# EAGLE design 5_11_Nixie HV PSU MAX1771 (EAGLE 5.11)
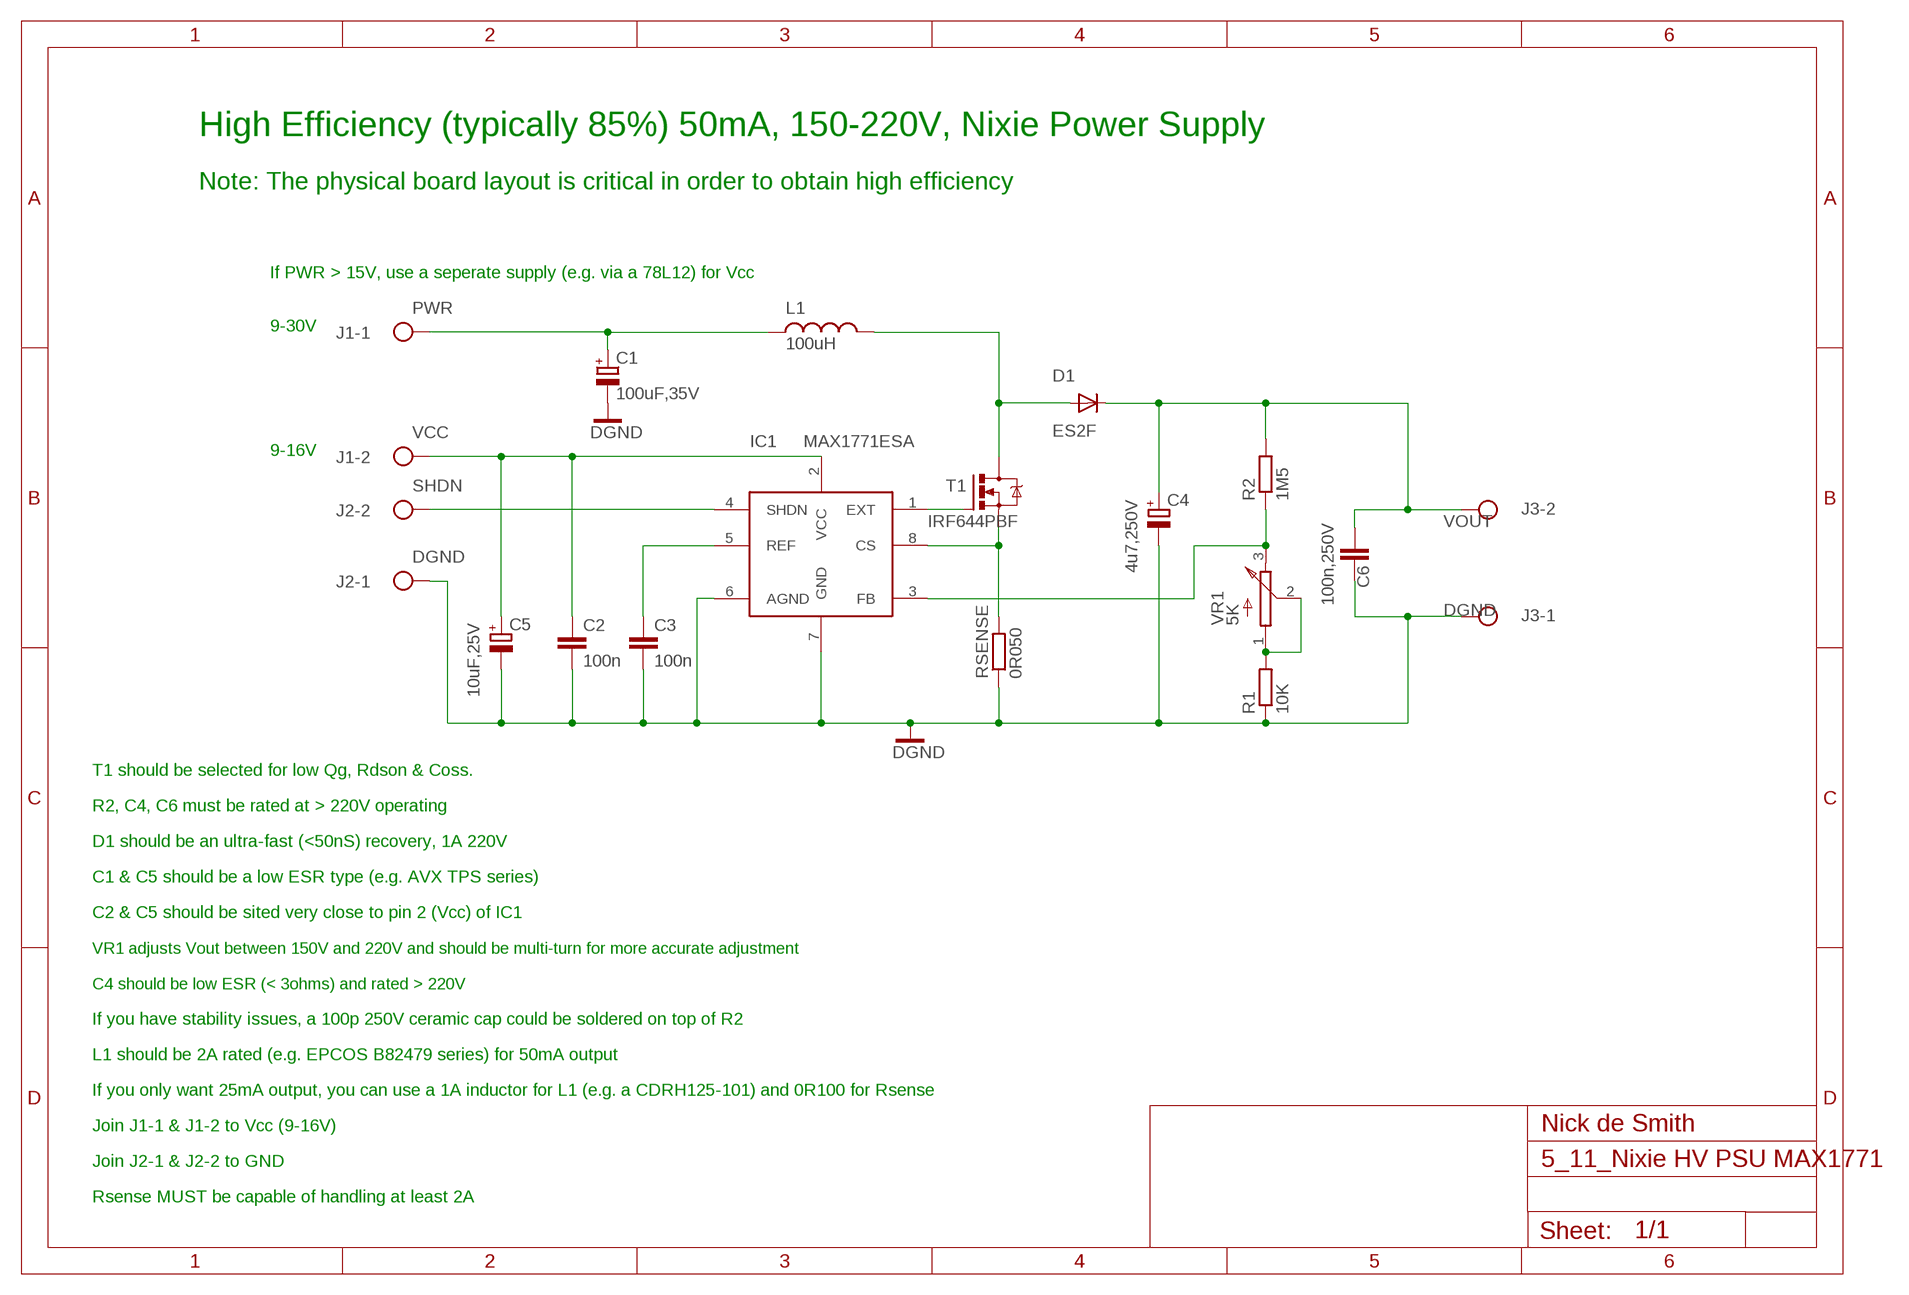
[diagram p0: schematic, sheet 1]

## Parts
C1  100uF,35V  C-POL-EU7343  [C-EIA-7343]
C2  100n  C-EUC0805  [C0805]
C3  100n  C-EUC0805  [C0805]
C4  4u7,250V  C-POL-EU-NICHICON-UJ-12  [NICHICON-UJ-12]
C5  10uF,25V  C-POL-EU7343  [C-EIA-7343]
C6  100n,250V  C-EU-2420  [C2420]
D1  ES2F  DIODE-SMC  [SMC]
IC1  MAX1771ESA  [SO-8]
J1  TERM-BLOCK-2-02IN  [SCREW-2-02]
J2  TERM-BLOCK-2-02IN  [SCREW-2-02]
J3  TERM-BLOCK-2-02IN  [SCREW-2-02]
L1  100uH  L-SMT-POWER-B82479  [L-B82479]
R1  10K  R-EU_R0805  [R0805]
R2  1M5  R-EU_R2512  [R2512]
RSENSE  0R050  R-EU_R2010  [R2010]
T1  IRF644PBF  IRF740  [TO220BV]
VR1  5K  TRIMPOT-3214W  [BOURNS-3214W]

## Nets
DGND [power]: C1.- C2.2 C3.2 C4.1(-) C5.- C6.P$2 IC1.6(AGND) IC1.7(GND) J2.1 J3.1 R1.1 RSENSE.1
EXT: IC1.1(EXT) T1.G
N$2: IC1.8(CS) RSENSE.2 T1.S
N$3: R1.2 VR1.1(A) VR1.2(W)
N$8: IC1.3(FB) R2.1 VR1.3(B)
N$15 [power]: D1.A L1.P$2 T1.D
N$17: C3.1 IC1.5(REF)
PWR [power]: C1.+ J1.1 L1.P$1
SHDN: IC1.4(SHDN) J2.2
VCC [power]: C2.1 C5.+ IC1.2(VCC) J1.2
VOUT [power]: C4.2(+) C6.P$1 D1.C J3.2 R2.2

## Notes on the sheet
- High Efficiency (typically 85%) 50mA, 150-220V, Nixie Power Supply
- Note: The physical board layout is critical in order to obtain high efficiency
- If PWR > 15V, use a seperate supply (e.g. via a 78L12) for Vcc
- 9-30V
- 9-16V
- T1 should be selected for low Qg, Rdson & Coss.
- R2, C4, C6 must be rated at > 220V operating
- D1 should be an ultra-fast (<50nS) recovery, 1A 220V
- C1 & C5 should be a low ESR type (e.g. AVX TPS series)
- C2 & C5 should be sited very close to pin 2 (Vcc) of IC1
- VR1 adjusts Vout between 150V and 220V and should be multi-turn for more accurate adjustment
- C4 should be low ESR (< 3ohms) and rated > 220V
- If you have stability issues, a 100p 250V ceramic cap could be soldered on top of R2
- L1 should be 2A rated (e.g. EPCOS B82479 series) for 50mA output
- If you only want 25mA output, you can use a 1A inductor for L1 (e.g. a CDRH125-101) and 0R100 for Rsense
- Join J1-1 & J1-2 to Vcc (9-16V) | Nick de Smith
- Join J2-1 & J2-2 to GND
- Rsense MUST be capable of handling at least 2A

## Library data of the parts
C1 C5 = nick:C-POL-EU7343: Capacitor, Tantalum, EU 7343 case, polarised
C2 C3 = rcl:C-EU: CAPACITOR, European symbol
C4 = nick:C-POL-EU: Capacitor, Tantalum, EU 7343 case, polarised
C6 = nick:C-EU
D1 = diode:DIODE-: DIODE
IC1 = nick:MAX1771
J1-J3 = nick:TERM-BLOCK-2
L1 = nick:L-SMT-POWER: SMT power inductors
R1 R2 RSENSE = rcl:R-EU_: RESISTOR, European symbol
T1 = transistor-power:IRF740: N-CHANNEL MOS FET
VR1 = nick:TRIMPOT

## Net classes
1 power: width 0.762 mm, clearance 0.508 mm

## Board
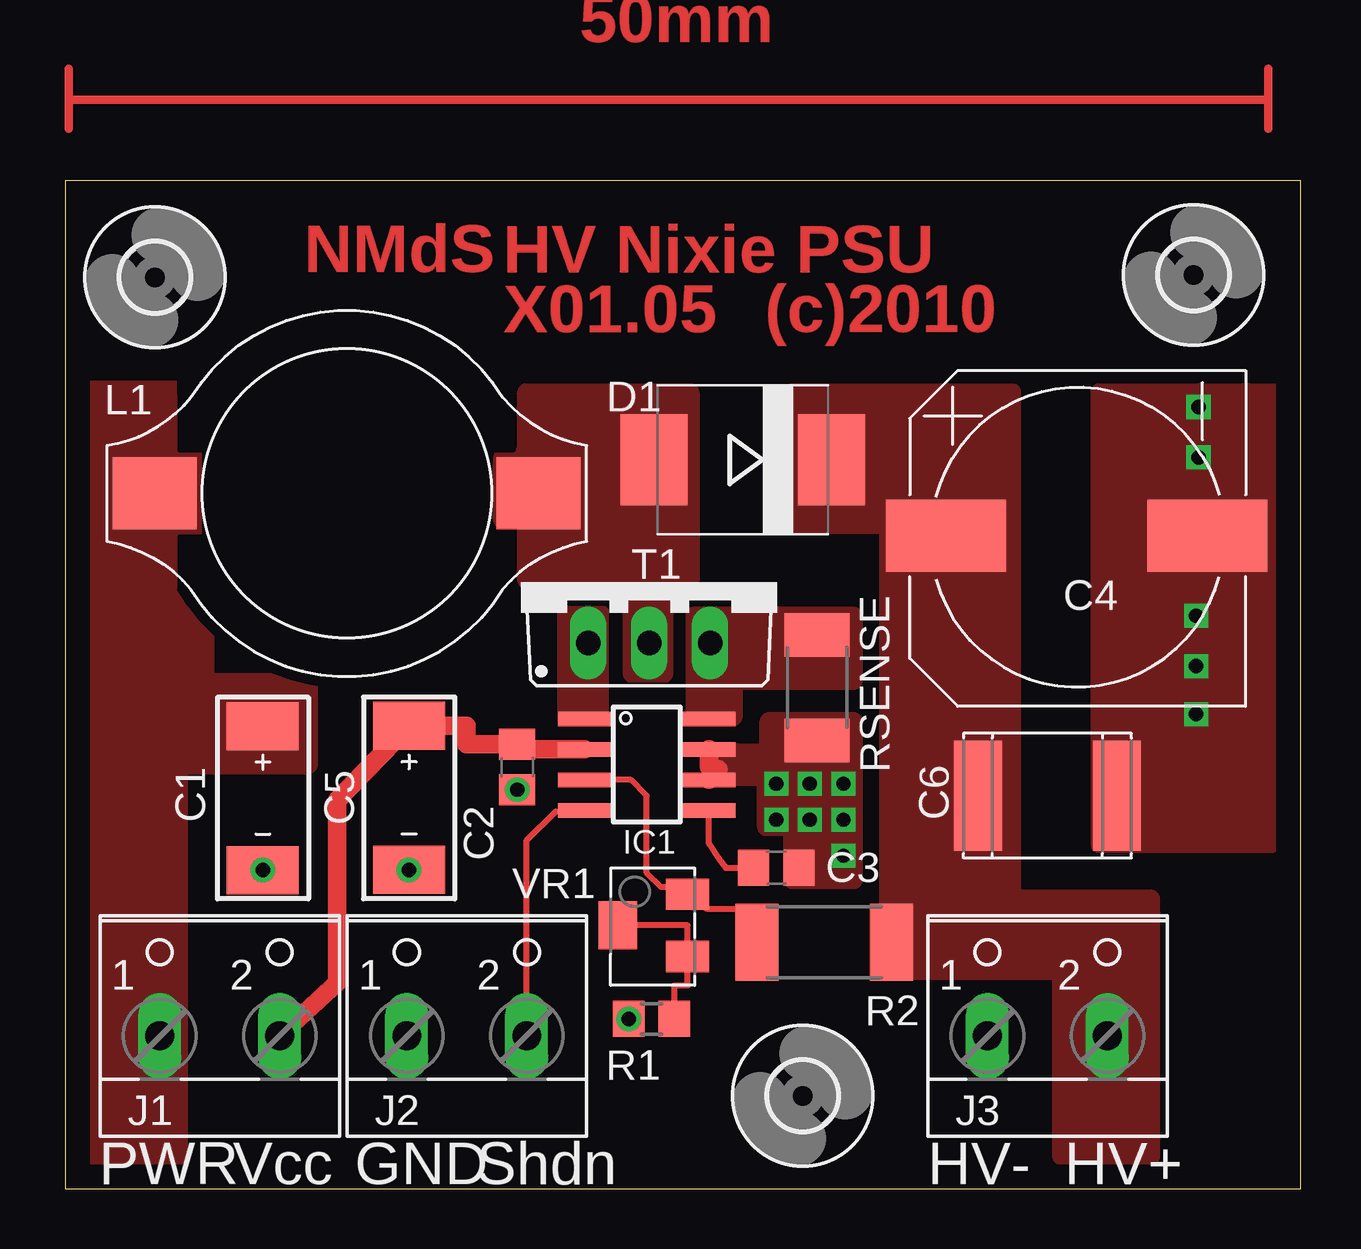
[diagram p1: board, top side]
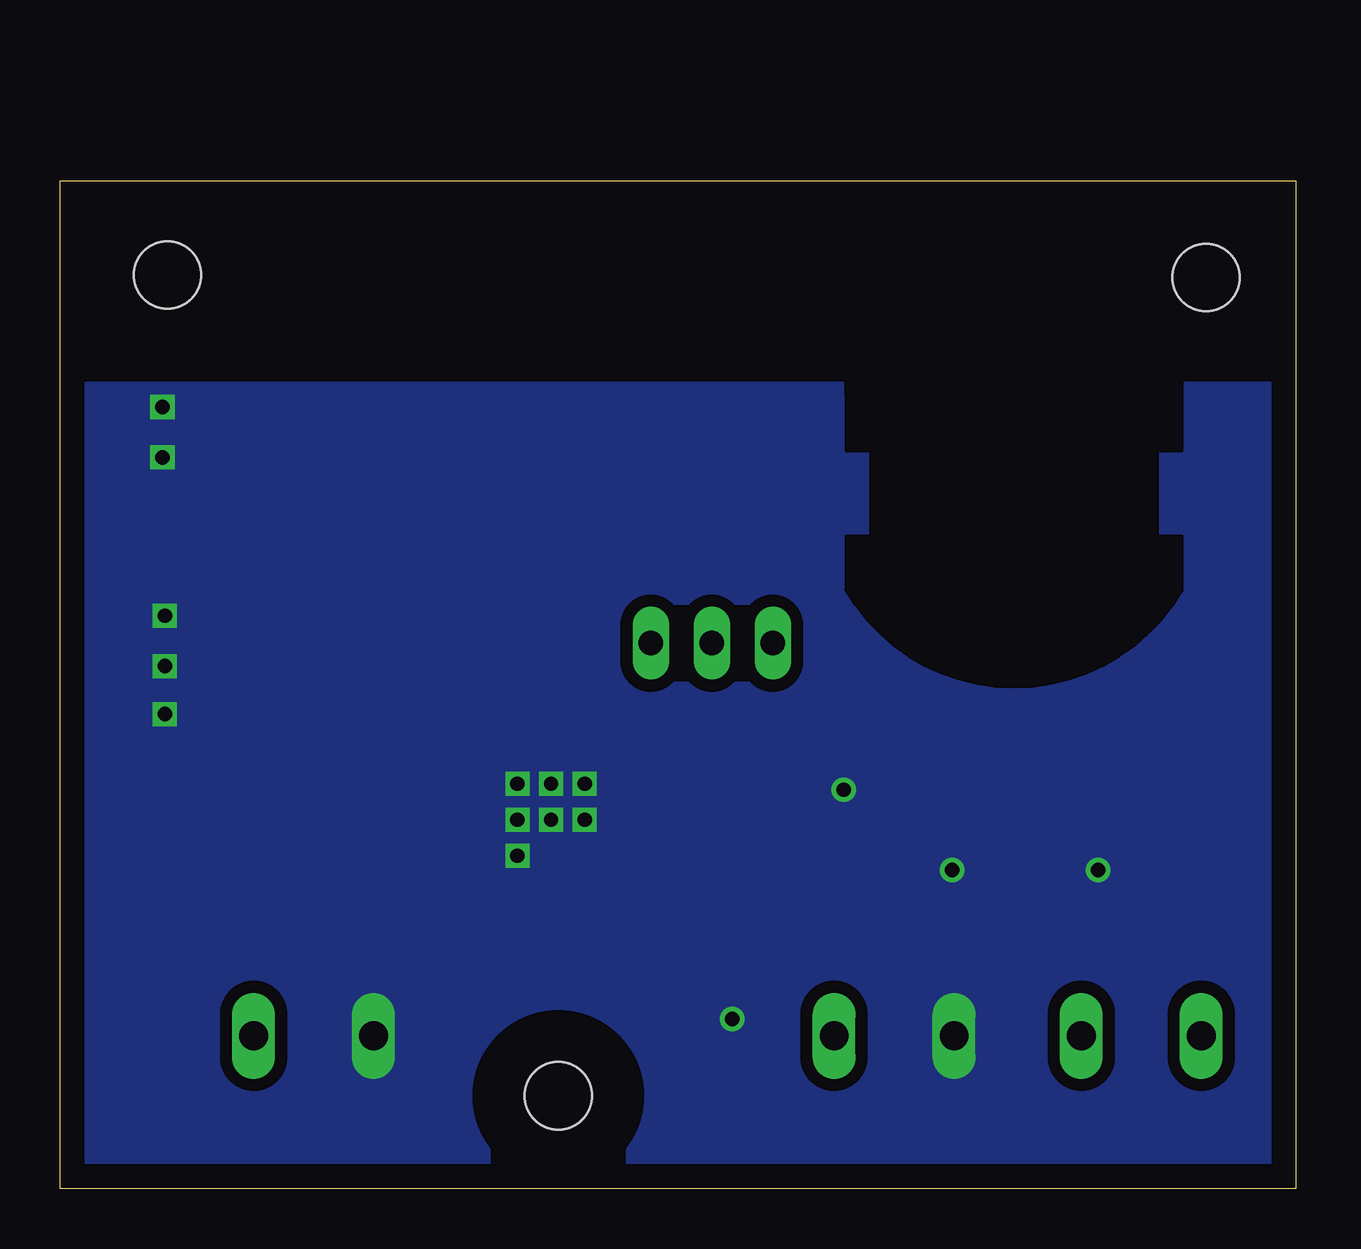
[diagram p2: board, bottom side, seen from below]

Size 51.5 x 42 mm. Coordinates in mm from the lower left corner, seen from the top.
Outline: 0,0 51.5,0 51.5,42 0,42 0,0
Copper layers (1*16): Top 0.035mm / dielectric 1.5mm / Bottom 0.035mm
Design rules "Olimex 10mils *": minimum track width 10mil, minimum drill 0.6mm, track to track 10mil, track to pad 10mil, pad to pad 10mil, via to via 10mil, smd to smd 10mil, copper to edge 40mil, drill to drill 10mil, minimum pad ring 10mil, minimum via ring 8mil, stop-mask expansion 0mil, vias tented up to drill 0mil, thermal gap 10mil

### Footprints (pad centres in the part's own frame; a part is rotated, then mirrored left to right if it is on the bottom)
C-EIA-7343 = smd 2 x 3: + -3,0; - 3,0
C0805 = smd 1.3 x 1.5: 1 -0.95,0; 2 0.95,0
NICHICON-UJ-12 = smd 3 x 5: 1 -2.4,-7.6; 2 -2.4,3.3
C2420 = smd 2 x 4.6: P$1 2.9,0; P$2 -2.9,0
SMC = smd 2.8 x 3.8: A 3.7,0; C -3.7,0
SO-8 = smd 0.6 x 2.2: 1 -1.905,-2.6; 2 -0.635,-2.6; 3 0.635,-2.6; 4 1.905,-2.6; 5 1.905,2.6; 6 0.635,2.6; 7 -0.635,2.6; 8 -1.905,2.6
SCREW-2-02 = drill 1.194 long: 1 -2.5,0; 2 2.5,0
L-B82479 = smd 3.5 x 3: P$1 -8,0; P$2 8,0
R0805 = smd 1.3 x 1.5: 1 -0.95,0; 2 0.95,0
R2512 = smd 1.8 x 3.2: 1 -2.8,0; 2 2.8,0
R2010 = smd 1.8 x 2.7: 1 -2.2,0; 2 2.2,0
TO220BV = drill 1.016 long: D 0,-2.54; G -2.54,-2.54; S 2.54,-2.54
2,8 = hole 2.8: 0,0
BOURNS-3214W = smd 1.8 x 1.3: 1 1.4,-1.3; 3 1.4,1.3 | smd 1.6 x 2: 2 -1.5,0

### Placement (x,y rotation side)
C1  8.23,16.27 270 top
C2  18.83,17.57 270 top
C3  29.63,13.37 0 top
C4  39.99,29.6 90 top
C5  14.32,16.28 270 top
C6  40.93,16.37 180 top
D1  28.23,30.37 180 top
IC1  24.23,17.67 270 top
J1  6.43,6.37 0 top
J2  16.73,6.37 0 top
J3  40.93,6.37 0 top
L1  11.73,28.97 0 top
R1  24.43,7.07 0 top
R2  31.63,10.27 0 top
RSENSE  31.33,20.87 90 top
T1  24.33,25.27 0 top
U$2  [2,8]  3.73,37.97 0 top
U$3  [2,8]  47.02,38.07 0 top
U$4  [2,8]  30.73,3.87 0 top
VR1  24.53,10.97 0 top

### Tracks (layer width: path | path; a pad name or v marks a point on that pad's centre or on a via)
DGND  (via drill 0.6, 0.6 pad 1.02)
  Top 0.762: IC1.6 26.93,17.07 27.23,17.17 | 27.23,17.47 26.93,17.47 26.83,17.57 IC1.7
  other vias: 29.63,16.87 31.03,15.37 32.43,13.87 32.43,15.37 32.43,16.87 31.03,16.87 29.63,15.37 47.13,23.87 47.13,21.77 47.13,19.77 23.48,7.07 14.32,13.28 8.23,13.27 18.83,16.62 47.23,30.47 47.23,32.57
  pour Bottom (isolate 0.01, rank 3, no thermals): 0.73,33.23 50.33,33.23 50.33,0.57 0.73,0.57
  pour Top (no thermals): 27.23,17.17 27.23,18.17 29.33,18.17 29.33,19.47 32.83,19.47 32.83,12.87 30.33,12.87 30.33,15.07 29.23,15.07 29.23,17.17
  pour Top (rank 2, no thermals): 43.13,33.17 50.33,33.17 50.23,14.37 43.13,14.37
EXT
  pour Top (no thermals): 20.73,24.07 22.43,24.07 22.43,19.47 20.73,19.47
N$1
  Top 0.358: 0.13,45.37 0.13,46.67 | 0.13,45.37 0.13,44.17 | 0.13,45.37 50.13,45.37 | 50.13,45.37 50.13,46.67 | 50.13,45.37 50.13,44.17
N$2
  pour Top (no thermals): 26.26,19.67 26.26,23.87 32.83,23.87 32.83,21.17 27.83,21.17 27.83,19.67
N$3
  Top 0.254: VR1.2 25.93,10.97 VR1.1 25.93,8.47 25.38,8.47 R1.2
N$8
  Top 0.254: IC1.3 23.57,17.04 24.23,16.37 24.23,13.17 24.83,12.57 25.93,12.57 VR1.3 26.73,11.67 28.03,11.67 R2.1
N$15
  pour Top (rank 2, no thermals): 19.23,30.47 19.23,33.17 26.03,33.17 26.03,25.37 24.93,25.37 24.93,21.47 23.63,21.47 23.63,25.37 19.23,25.37 19.23,27.87 18.23,27.87 18.23,30.47
N$17
  Top 0.254: C3.1 27.53,13.37 27.23,13.77 26.83,14.37 IC1.5
PWR
  pour Top (isolate 0.01, rank 2, no thermals): 4.73,17.67 10.13,17.67 10.13,21.07 5.83,21.07 5.83,33.27 0.73,33.27 0.73,1.37 4.73,1.37
SHDN
  Top 0.254: J2.2 19.23,14.51 20.43,15.71 IC1.4
VCC
  Top 0.762: J1.2 11.33,8.57 11.33,16.18 C5.+ 16.73,19.28 16.73,18.52 C2.1 18.83,18.3 IC1.2
VOUT
  pour Top (isolate 0.01, rank 2, no thermals): 30.33,33.17 39.43,33.17 39.43,12.07 45.23,12.07 45.23,1.37 41.53,1.37 41.53,9.07 34.33,9.07 34.33,27.67 30.33,27.67

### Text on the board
Top: 50mm | NMdS | HV Nixie PSU | X01.05 | (c)2010
tPlace: PWR | Vcc | GND | Shdn | HV- | HV+
Measures: 0.000 | 0.146 | 1.839 | 1.655 | 1.512 | 1.508 | 0.154 | 0.000 | 0.000 | 0.001 | 0.000 | 0.001 | 0.000 | 0.000 | 1.209 | 2.026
